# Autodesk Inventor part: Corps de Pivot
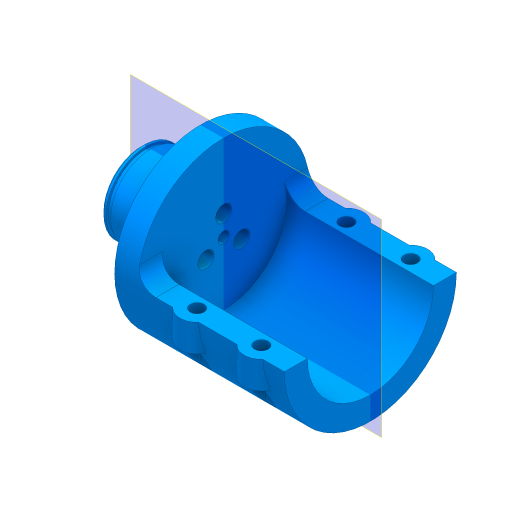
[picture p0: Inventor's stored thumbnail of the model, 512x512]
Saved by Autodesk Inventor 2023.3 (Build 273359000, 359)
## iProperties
Created: 2020-12
Part Number: Corps de Pivot
Material: Générique
Document SubType Name: Modeling
Designer: Joffre.gerschheimer
Density: 1 g/cm^3
Appearance: Par défaut(1)
Author: Joffre.gerschheimer
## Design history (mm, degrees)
sketch "Esquisse1"
  geometry: L1 (99.75, -37.5)-(25.75, -37.5); L2 (99.75, -37.5)-(99.75, 0); L3 (99.75, 0)-(0, 0); L4 (25.75, -37.5)-(25.75, 0); L5 (17.75, 0)-(17.75, -23.97); L6 (17.75, -23.97)-(25.75, -23.97); L7 (4, 0)-(4, -17.5); L8 (4, -17.5)-(17.75, -17.5); L9 (2, 0)-(2, -16.5); L10 (2, -16.5)-(4, -16.5); L11 (1, 0)-(1, -17.5); L12 (1, -17.5)-(2, -17.5); L13 (2, -16.5)-(2, -17.5); L14 (1, -16.5)-(0, -16.5); L15 (0, -16.5)-(0, 0); L16 (1, -16.5)-(1, -17.5); L17 (1, -17.5)-(0, -16.5); 1 further point
  constraints: 34 end point, 12 point on line, 8 perpendicular, 4 vertical, 2 horizontal, 1 coincident, 1 parallel
  dimensions: "d10" = 74 distance of L1.start L1.end; "d12" = 13.75 distance of L7.end L8.end; "d13" = 8 distance of L5.end L6.end; "d14" = 2 distance of L9.end L10.end; "d15" = 1 distance of L11.end L12.end; "d16" = 1 distance of L14.start L14.end; "d17" = 37.5 distance of L1.end L4.end; "d18" = 23.97 distance of L5.start L5.end; "d19" = 17.5 distance of L7.start L7.end; "d20" = 16.5 distance of L9.start L9.end; "d21" = 17.5 distance of L11.start L11.end (derived); "d22" = 16.5 distance of L14.end L3.end
revolve "Révolution1" sketch "Esquisse1" stored, may be unused: angle "d23" = 90 deg
sketch "Esquisse3"
  geometry: L1 (0, -37.5)-(0, 0); L2 (0, 0)-(0, 37.5); A1 r 37.5 centre (0, 0) between (0, -37.5) and (0, 37.5) reference; 1 further point
  constraints: 4 end point, 2 point on circle, 1 point on line, 1 vertical
extrude "Extrusion1" cut sketch "Esquisse3" distance "d24" = 64; taper "d25" = 0 deg
fillet "Congé1" dims "d26" = 8
sketch "Esquisse4"
  geometry: L1 (0, 37.5)-(0, -37.5) reference; C1 r 27.5 at (0, 0); 1 further point
  constraints: 1 centre point, 1 midpoint
  dimensions: "d27" = 55 diameter of C1
extrude "Extrusion2" cut sketch "Esquisse4" distance "d28" = 64; taper "d29" = 0 deg
fillet "Congé2" dims "d30" = 8
sketch "Esquisse5"
  geometry: L1 (0, 10)-(0, 0) reference; L2 (0, 0)-(-56, 0) reference; L3 (-7.5, 5.035)-(-22.5, 5.035); L4 (-64, 74.137)-(-64, 0.863) reference; A1 r 7.5 centre (-15, 4.955) between (-22.5, 5.035) and (-7.5, 5.035); 6 further points
  constraints: 2 end point, 2 midpoint, 2 point on circle, 1 centre point, 1 coincident
  dimensions: "d31" = 15 distance from line of L1 point (-15, 4.955); "d35" = 15 diameter of A1; "d87" = 32.465 vertical distance of point (-64, 37.5) point (-15, 5.035); "d100" = 4.955 distance from line of L2 point (-15, 4.955)
extrude "Extrusion3" join sketch "Esquisse5" distance "d37" = 12; taper "d38" = 0 deg
sketch "Esquisse10"
  geometry: 2 further points
hole "Perçage2" sketch "Esquisse10" at (0, 0) diameter "d68" = 4.917; stored, may be unused: countersink angle "d72" = 90 deg, drill point angle "d74" = 118 deg; dims "d69" = 12, "d70" = 4, "d71" = 2, "d73" = 8
sketch "Esquisse12"
  geometry: 1 further point
sketch "Esquisse13"
  geometry: 3 further points
  dimensions: "d76" = 9 distance of point (0, 0) point (9, 0)
hole "Perçage3" sketch "Esquisse13" at (9, 0) diameter "d77" = 7; stored, may be unused: countersink angle "d81" = 90 deg, drill point angle "d83" = 118 deg; dims "d78" = 6, "d79" = 9, "d80" = 2, "d82" = 8
pattern_circular "Réseau circulaire1" dims angle "d85" = 360 deg
sketch "Esquisse15"
  geometry: L1 (0, 65)-(0, 10) reference; C1 r 3 at (-15, 4.955); A1 r 7.5 centre (-15, 4.955) between (-20.63, 0) and (-9.37, 0) reference; 2 further points
  constraints: 1 centre point, 1 coincident, 1 midpoint
  dimensions: "d88" = 6 diameter of C1
extrude "Extrusion6" cut sketch "Esquisse15" extent not by distance; stored distance "d90" = 0; taper "d91" = 0 deg
sketch "Esquisse16"
  geometry: L1 (10.381, 4.955)-(12.691, 8.955); L2 (12.691, 8.955)-(17.309, 8.955); L3 (17.309, 8.955)-(19.619, 4.955); L4 (19.619, 4.955)-(17.309, 0.955); L5 (17.309, 0.955)-(12.691, 0.955); L6 (12.691, 0.955)-(10.381, 4.955); L7 (0, 10)-(0, 0) reference; A1 r 7.5 centre (15, 4.955) between (8.119, 1.972) and (21.881, 1.972) reference; 2 further points
  constraints: 12 end point, 1 coincident, 1 perpendicular, 13 other
  dimensions: "d92" = 8 distance between parallel lines of L2 L5
extrude "Extrusion7" cut sketch "Esquisse16" distance "d93" = 30; taper "d95" = 0 deg; dims "d94" = 5, "d96" = 0
pattern_linear "Réseau rectangulaire1" dims "d99" = 28
mirror "Symétrie2"
node "Solide1"
